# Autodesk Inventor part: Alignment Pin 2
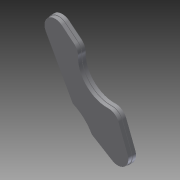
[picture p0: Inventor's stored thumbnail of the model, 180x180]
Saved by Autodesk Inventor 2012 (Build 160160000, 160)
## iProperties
Created: 2013-01
Part Number: Alignment Pin 2
Material: Default
Document SubType Name: Modeling
Designer: Alex
Density: 1 g/cm^3
Mass: 0.0632802 g
Surface Area: 1.67304 cm^2
Volume: 0.0632802 cm^3
Author: Alex
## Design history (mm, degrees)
sketch "Sketch1" dims "d9" = 26.9875
  geometry: L1 (0, 0)-(48.768, 0); L2 (0, 0)-(48.768, 0); L3 (0, 0)-(-33.222, 0); L4 (0, 48.768)-(0, 0); L5 (0, 0)-(-16.68, 45.827); L6 (0, 0)-(-24.384, 42.234); L7 (0, 0)-(-31.347, 37.358); L8 (-4.851, 23.047)-(-4.771, 17.498); L9 (-9.731, 31.291)-(-5.061, 23.62); L10 (-13.426, 23.255)-(-11.534, 23.55); L11 (-15.678, 14.644)-(-12.768, 12.88); L12 (0, 0)-(-6.814, 14.613); L13 (-8.468, 48.027)-(0, 0); L14 (-15.756, 39.838)-(-13.817, 27.326); L15 (-1.558, 32.732)-(-1.999, 30.481); L16 (-13.538, 40.645)-(-6.668, 29.276); L17 (-1.199, 42.825)-(-3.751, 29.792); L18 (-22.233, 24.073)-(-18.39, 17.098); L19 (-19.847, 26.076)-(-18.104, 24.672); L20 (-13.896, 25.106)-(-18.935, 24.191); L21 (-13.426, 23.255)-(-14.628, 21.764); L22 (1.558, 32.732)-(1.999, 30.481); L23 (-10.46, 14.817)-(-11.755, 18.156); L24 (-26.609, 33.577)-(-16.758, 25.626); L25 (-28.446, 32.035)-(-22.023, 20.41); L26 (-36.497, 22.434)-(-23.926, 18.14); C1 r 6.35 at (0, 0); C2 r 14.287 at (0, 0); C3 r 42.428 at (0, 0); C4 r 50.864 at (0, 0); C5 r 2.083 at (0, 23.812); C6 r 5.652 at (0, 23.812); A1 r 23.812 centre (0, 0) between (-3.351, 23.576) and (0, 23.812); A2 r 48.768 centre (0, 0) between (0, 48.768) and (-16.68, 45.827); A3 r 1.588 centre (-6.358, 17.453) between (-7.602, 16.467) and (-4.771, 17.498); A4 r 1.587 centre (-6.419, 22.799) between (-4.851, 23.047) and (-5.061, 23.62); A5 r 1.588 centre (-5.309, 30.097) between (-6.668, 29.276) and (-3.751, 29.792); A6 r 1.588 centre (-0.441, 30.176) between (-1.999, 30.481) and (-0.331, 28.592); A7 r 1.587 centre (0.441, 30.176) between (0.331, 28.592) and (1.999, 30.481); A8 r 4.791 centre (0, 23.812) between (0.331, 28.592) and (-0.331, 28.592); A9 r 4.064 centre (0, 23.812) between (-0.522, 19.782) and (-0.571, 19.789); A10 r 44.806 centre (0, 0) between (-2.858, 44.714) and (-12.627, 42.99); A11 r 1.587 centre (-20.844, 24.841) between (-19.847, 26.076) and (-22.233, 24.073); A12 r 1.587 centre (-19.1, 23.436) between (-17.514, 23.385) and (-18.104, 24.672); A13 r 1.587 centre (-16.877, 27.763) between (-17.874, 26.527) and (-15.912, 26.502); A14 r 4.089 centre (-13.426, 23.255) between (-17.514, 23.385) and (-13.289, 19.168); A15 r 1.587 centre (-15.605, 28.497) between (-14.996, 27.031) and (-14.036, 28.74); A16 r 1.587 centre (-11.091, 30.472) between (-9.731, 31.291) and (-12.659, 30.226); A17 r 1.588 centre (-2.757, 43.13) between (-1.199, 42.825) and (-2.858, 44.714); A18 r 1.588 centre (-12.179, 41.466) between (-12.627, 42.99) and (-13.538, 40.645); A19 r 1.587 centre (0, 32.427) between (1.558, 32.732) and (-1.558, 32.732); A20 r 1.588 centre (-11.936, 14.232) between (-12.768, 12.88) and (-10.46, 14.817); A21 r 1.588 centre (-15.279, 26.468) between (-14.995, 24.906) and (-14.455, 25.111); A22 r 1.587 centre (-13.235, 17.581) between (-11.755, 18.156) and (-13.289, 19.168); A23 r 1.588 centre (-17.324, 39.594) between (-15.756, 39.838) and (-17.961, 41.048); A24 r 44.806 centre (0, 0) between (-17.961, 41.048) and (-26.552, 36.091); A25 r 48.768 centre (0, 0) between (-14.134, 46.675) and (-15.063, 46.383); A26 r 1.587 centre (-16.534, 16.959) between (-17.925, 16.192) and (-17.533, 15.725); A27 r 5.652 centre (-20.622, 11.906) between (-22.847, 6.711) and (-18.39, 17.098); A28 r 1.588 centre (-25.611, 34.812) between (-26.552, 36.091) and (-26.609, 33.577); A29 r 44.806 centre (0, 0) between (-30.931, 32.416) and (-37.306, 24.816); A30 r 1.588 centre (-29.836, 31.267) between (-28.446, 32.035) and (-30.931, 32.416); A31 r 1.588 centre (-35.984, 23.936) between (-37.306, 24.816) and (-36.497, 22.434); A32 r 1.588 centre (-23.413, 19.643) between (-23.926, 18.14) and (-22.023, 20.41); 16 further points
  constraints: 78 point on circle, 52 end point, 38 centre point, 34 symmetric about line, 21 tangent, 18 point on line, 9 coincident, 3 equal radius, 2 concentric, 2 equal length, 2 horizontal, 1 collinear, 1 parallel, 1 perpendicular, 1 vertical, 1 vertical alignment, 16 other
  dimensions: "d0" = 12.7 diameter of C1; "d1" = 28.575 diameter of C2; "d2" = 3.9624 radial gap between concentric circles of A10 A2; "d3" = 89.6112 diameter of A10 (derived); "d4" = 47.625 diameter of A1; "d5" = 20 deg angle of L5 L4; "d6" = 1.5875 distance between parallel lines of L17 L15; "d7" = 0.79375 distance from line of L13 A1.start; "d8" = 84.85676 diameter of C3; "d10" = 1.5875 radius of A5; "d11" = 1.5875 radius of A18; "d12" = 4.1656 diameter of C5; "d13" = 1.5875 radius of A6; "d14" = 120 deg angle of L2 L6; "d15" = 130 deg angle of L1 L7; "d16" = 4.064 radius of A9; "d17" = 18.8581 deg angle of L3 L26; "d18" = 31.2127 deg angle of L3 L11; "d19" = 61.1419 deg angle of L3 L18; "d20" = 1.5875 radius of A11; "d21" = 1.5875 radius of A20; "d22" = 1.39036 horizontal distance of A26.centre A26.start; "d23" = 1.5875 radius of A26; "d24" = 1.23386 vertical distance of A26.centre A26.end; "d25" = 5.54975 distance of A26.end L11.end; "d26" = 2.30817 horizontal distance of L23.start L11.end; "d27" = 1.93678 vertical distance of L23.start L11.end; "d28" = 8.98152 distance of L18.start A26.start; "d29" = 0.44088 distance from line of L4 A7.centre; "d30" = 1.905 distance from line of L10.start L20; "d31" = 8.1788 diameter of A14; "d32" = 11.14 deg angle of L19 L7; "d33" = 3.175 diameter of A12; "d34" = 18.79 deg angle of L23 L7; "d35" = 3.175 diameter of A22; "d36" = 42.2839 deg angle of L14 L24; "d37" = 1.58758 distance from line of L19 L24.end; "d38" = 3.175 diameter of A13; "d39" = 3.175 diameter of A15; "d40" = 26.85263 distance of A10.centre L10.start; "d41" = 0.0625 deg angle of L18 L25; "d42" = 1.5875 radial gap between concentric circles of C6 A9; "d43" = 5 deg angle of L6 L12; "d44" = 2.91009 horizontal distance of L11.start L11.end; "d45" = 2.71168 horizontal distance of L11.start L18.end
extrude "Extrusion1" new body sketch "Sketch1" distance "d46" = 1.016; taper "d47" = 0 deg
sketch "Sketch2"
  geometry: L1 (-12.768, 12.88)-(-15.678, 14.644) reference; L2 (-11.755, 18.156)-(-10.46, 14.817) reference; L3 (-19.847, 26.076)-(-18.104, 24.672) reference; L4 (-18.39, 17.098)-(-22.233, 24.073) reference; L5 (-11.826, 18.128)-(-10.531, 14.789); L6 (-12.728, 12.946)-(-15.621, 14.698); L7 (-18.336, 17.158)-(-22.168, 24.111); L8 (-19.896, 26.018)-(-18.152, 24.613); A1 r 5.651 centre (-20.622, 11.906) between (-15.678, 14.644) and (-18.39, 17.098) reference; A2 r 1.588 centre (-11.936, 14.232) between (-12.768, 12.88) and (-10.46, 14.817) reference; A3 r 1.587 centre (-13.235, 17.581) between (-11.755, 18.156) and (-13.289, 19.168) reference; A4 r 4.089 centre (-13.426, 23.255) between (-17.514, 23.385) and (-13.289, 19.168) reference; A5 r 1.587 centre (-19.1, 23.436) between (-17.514, 23.385) and (-18.104, 24.672) reference; A6 r 1.588 centre (-20.844, 24.841) between (-19.847, 26.076) and (-22.233, 24.073) reference; A7 r 1.511 centre (-19.1, 23.436) between (-17.59, 23.388) and (-18.152, 24.613); A8 r 4.166 centre (-13.426, 23.255) between (-17.59, 23.388) and (-13.286, 19.092); A9 r 1.511 centre (-13.235, 17.581) between (-11.826, 18.128) and (-13.286, 19.092); A10 r 1.511 centre (-11.936, 14.232) between (-12.728, 12.946) and (-10.531, 14.789); A11 r 5.728 centre (-20.622, 11.906) between (-15.621, 14.698) and (-18.336, 17.158); A12 r 1.511 centre (-20.844, 24.841) between (-19.896, 26.018) and (-22.168, 24.111); 1 further point
  constraints: 12 point on circle, 8 end point, 6 centre point, 9 other
  dimensions: "d48" = 0.0762 distance between parallel lines of L3 L8
extrude "Extrusion2" cut sketch "Sketch2" distance "d49" = 0.508; taper "d50" = 0 deg
body "Solid1"
